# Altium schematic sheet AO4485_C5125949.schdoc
size 127 x 101 mm
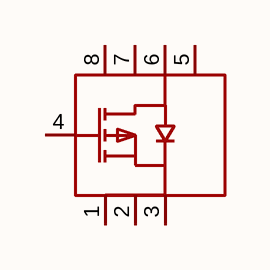
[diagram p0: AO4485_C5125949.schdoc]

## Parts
Q?  ao4485_c5125949  [SOP-8_L4.9-W3.9-P1.27-LS6.0-BL]  (value not drawn)

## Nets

Not connected (* = marked no-connect by the designer): Q? 1(S) 2(S) 3(S) 4(G) 5(D) 6(D) 7(D) 8(D)

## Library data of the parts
Q? = ao4485_c5125949: 数量:1个P沟道;漏源电压(Vdss):40V;连续漏极电流(Id):12A;导通电阻(RDS(on)):12.5mΩ@10V；16mΩ@4.5V;耗散功率(Pd):3.1W;阈值电压(Vgs(th)):1.5V;; Manufacturer: UMW(友台半导体); ManufacturerPart: AO4485; AddInBom: yes; ModelId: 75c24a7891ee4dd6bdac16a7163ff87e; ModelName: SOP-8_L4.9-W3.9-P1.27-LS6.0-BL-1; ModelTransform: 192.913,236.22,0,0,0,0,-0.393,2.749,0; Number: 1个P沟道; Drain to Source Voltage: 40V; Current - Continuous Drain(Id): 12A; Pd - Power Dissipation: 3.1W; Gate Threshold Voltage (Vgs(th)): 1.5V; Gate Charge(Qg): 42nC@10V; Input Capacitance(Ciss): 2.5nF; Reverse Transfer Capacitance (Crss@Vds): 180pF; Output Capacitance(Coss): 260pF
